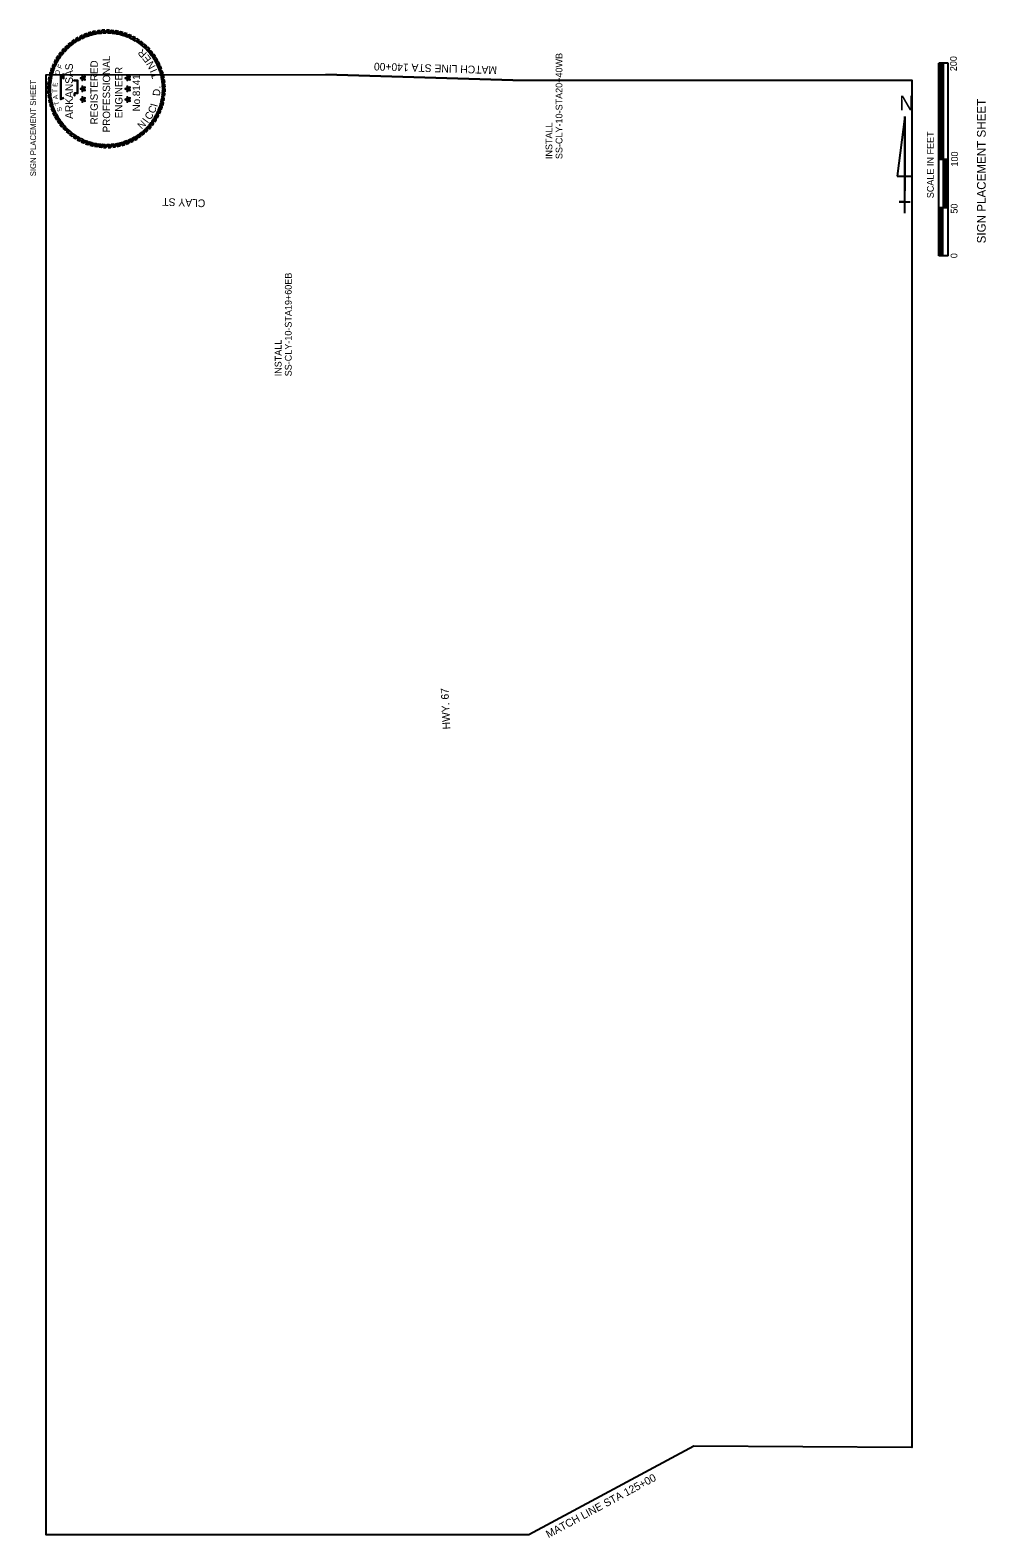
# Model space of a CAD drawing. Extents: x 992072 to 994297, y 1841240 to 1845659.
# Drawn here: x 992072 to 993062, y 1841240 to 1842803 of the extents above; entities that cross this region are included whole.
import ezdxf

# ---------------------------------------------------------------- set-up
doc = ezdxf.new("R2010")
doc.units = 0
for name, color, linetype in [('5', 7, 'Continuous'), ('63', 7, 'Continuous'), ('G-ANNO-SYMB', 7, 'Continuous'), ('G-ANNO-TEXT', 7, 'Continuous'), ('Level 10', 7, 'Continuous'), ('Plan Notes', 7, 'Continuous'), ('R_Annotation', 7, 'Continuous'), ('R_No Plot', 7, 'Continuous')]:
    doc.layers.add(name, color=color, linetype=linetype)

msp = doc.modelspace()

# ---------------------------------------------------------------- linework, layer by layer
at = {"layer": '5'}
for p, q in [((992572.2, 1842751.1), (992378.4, 1842757)), ((992759.9, 1841335.3), (992589, 1841243.7))]:
    msp.add_line(p, q, dxfattribs=at)
at = {"layer": '63'}
for p, q in [((992978.4, 1842713.3), (992970.7, 1842651.7)), ((992978.4, 1842613.3), (992978.4, 1842713.3)), ((992978.4, 1842713.3), (992978.4, 1842636.4)), ((992970.7, 1842651.7), (992986.1, 1842651.7)), ((992978.4, 1842613.3), (992978.4, 1842636.4)), ((992978.4, 1842624.8), (992972.6, 1842624.8)), ((992972.6, 1842624.8), (992984.1, 1842624.8)), ((992978.4, 1842613.3), (992978.4, 1842624.8))]:
    msp.add_line(p, q, dxfattribs=at)
at = {"layer": 'G-ANNO-SYMB'}
for points in [[(992117.9, 1842793), (992115.8, 1842791.5), (992114.5, 1842787), (992116.7, 1842788.7)], [(992122, 1842795.4), (992119.8, 1842794.1), (992118.1, 1842789.7), (992120.5, 1842791.3)], [(992126.3, 1842797.5), (992123.9, 1842796.4), (992122, 1842792.2), (992124.4, 1842793.5)], [(992130.7, 1842799.3), (992128.3, 1842798.4), (992126, 1842794.3), (992128.6, 1842795.5)], [(992135.3, 1842800.7), (992132.8, 1842800), (992130.2, 1842796.1), (992132.8, 1842797.1)], [(992139.9, 1842801.8), (992137.4, 1842801.3), (992134.5, 1842797.6), (992137.2, 1842798.4)], [(992144.7, 1842802.5), (992142.1, 1842802.2), (992138.9, 1842798.8), (992141.7, 1842799.3)], [(992149.4, 1842802.8), (992146.8, 1842802.7), (992143.4, 1842799.5), (992146.2, 1842799.8)], [(992154.2, 1842802.8), (992151.6, 1842802.8), (992147.9, 1842800), (992150.7, 1842800.1)], [(992158.9, 1842802.3), (992156.3, 1842802.6), (992152.5, 1842800), (992155.3, 1842799.9)], [(992163.7, 1842801.5), (992161.1, 1842802), (992157, 1842799.8), (992159.8, 1842799.4)], [(992168.3, 1842800.4), (992165.8, 1842801.1), (992161.5, 1842799.1), (992164.3, 1842798.6)], [(992172.8, 1842798.9), (992170.3, 1842799.7), (992166, 1842798.1), (992168.7, 1842797.4)], [(992177.2, 1842797), (992174.8, 1842798.1), (992170.3, 1842796.8), (992173, 1842795.8)], [(992181.4, 1842794.8), (992179.1, 1842796), (992174.6, 1842795.1), (992177.1, 1842793.9)], [(992185.5, 1842792.2), (992183.3, 1842793.7), (992178.6, 1842793.1), (992181.1, 1842791.7)], [(992103.8, 1842780.2), (992102.2, 1842778.1), (992102.4, 1842773.5), (992104, 1842775.8)], [(992107, 1842783.8), (992105.2, 1842781.9), (992105, 1842777.2), (992106.8, 1842779.4)], [(992110.4, 1842787.1), (992108.5, 1842785.3), (992107.9, 1842780.7), (992109.8, 1842782.8)], [(992114, 1842790.2), (992112, 1842788.6), (992111.1, 1842784), (992113.2, 1842785.9)], [(992189.3, 1842789.4), (992187.2, 1842791), (992182.6, 1842790.8), (992184.9, 1842789.2)], [(992192.9, 1842786.2), (992191, 1842788), (992186.3, 1842788.2), (992188.5, 1842786.4)], [(992196.2, 1842782.8), (992194.4, 1842784.7), (992189.8, 1842785.3), (992191.9, 1842783.4)], [(992199.3, 1842779.2), (992197.7, 1842781.2), (992193.1, 1842782.1), (992195, 1842780.1)], [(992202.1, 1842775.3), (992200.6, 1842777.4), (992196.1, 1842778.7), (992197.8, 1842776.5)], [(992094.3, 1842763.7), (992093.5, 1842761.2), (992095.1, 1842756.9), (992095.9, 1842759.6)], [(992096.2, 1842768.1), (992095.2, 1842765.7), (992096.4, 1842761.2), (992097.4, 1842763.9)], [(992098.4, 1842772.3), (992097.2, 1842770), (992098.1, 1842765.5), (992099.3, 1842768)], [(992101, 1842776.4), (992099.5, 1842774.2), (992100.1, 1842769.5), (992101.5, 1842772)], [(992204.5, 1842771.2), (992203.2, 1842773.5), (992198.8, 1842775.1), (992200.4, 1842772.7)], [(992206.6, 1842766.9), (992205.5, 1842769.3), (992201.3, 1842771.2), (992202.7, 1842768.8)], [(992208.4, 1842762.5), (992207.5, 1842764.9), (992203.4, 1842767.2), (992204.6, 1842764.6)], [(992209.8, 1842757.9), (992209.1, 1842760.4), (992205.2, 1842763), (992206.2, 1842760.4)], [(992090.9, 1842749.8), (992090.6, 1842747.2), (992093.2, 1842743.4), (992093.3, 1842746.2)], [(992091.7, 1842754.5), (992091.2, 1842752), (992093.4, 1842747.9), (992093.8, 1842750.7)], [(992092.8, 1842759.2), (992092.1, 1842756.7), (992094.1, 1842752.4), (992094.6, 1842755.2)], [(992126.9, 1842753.2), (992126.1, 1842753.8), (992124.2, 1842753.2), (992126.1, 1842752.5)], [(992126.9, 1842753.2), (992127.3, 1842754.2), (992126.1, 1842755.8), (992126.1, 1842753.8)], [(992126.9, 1842753.2), (992126.1, 1842752.5), (992126.1, 1842750.5), (992127.3, 1842752.2)], [(992126.9, 1842753.2), (992128, 1842753.2), (992129.2, 1842754.8), (992127.3, 1842754.2)], [(992126.9, 1842753.2), (992127.3, 1842752.2), (992129.2, 1842751.5), (992128, 1842753.2)], [(992173.5, 1842753.2), (992172.6, 1842753.8), (992170.7, 1842753.2), (992172.6, 1842752.5)], [(992173.5, 1842753.2), (992173.8, 1842754.2), (992172.6, 1842755.8), (992172.6, 1842753.8)], [(992173.5, 1842753.2), (992172.6, 1842752.5), (992172.6, 1842750.5), (992173.8, 1842752.2)], [(992173.5, 1842753.2), (992174.6, 1842753.2), (992175.7, 1842754.8), (992173.8, 1842754.2)], [(992173.5, 1842753.2), (992173.8, 1842752.2), (992175.7, 1842751.5), (992174.6, 1842753.2)], [(992210.9, 1842753.3), (992210.4, 1842755.8), (992206.7, 1842758.7), (992207.5, 1842756)], [(992211.6, 1842748.6), (992211.3, 1842751.1), (992207.9, 1842754.3), (992208.4, 1842751.5)], [(992211.9, 1842743.8), (992211.8, 1842746.4), (992208.6, 1842749.8), (992209, 1842747)], [(992090.4, 1842745.1), (992090.4, 1842742.5), (992093.2, 1842738.8), (992093.1, 1842741.6)], [(992090.4, 1842740.3), (992090.5, 1842737.7), (992093.7, 1842734.3), (992093.4, 1842737.1)], [(992090.7, 1842735.6), (992091, 1842733), (992094.5, 1842729.8), (992093.9, 1842732.6)], [(992091.4, 1842730.8), (992091.9, 1842728.3), (992095.6, 1842725.4), (992094.8, 1842728.1)], [(992126.9, 1842742.1), (992126.1, 1842742.7), (992124.2, 1842742.1), (992126.1, 1842741.4)], [(992126.9, 1842730.9), (992126.1, 1842731.6), (992124.2, 1842730.9), (992126.1, 1842730.3)], [(992126.9, 1842742.1), (992127.3, 1842743.1), (992126.1, 1842744.7), (992126.1, 1842742.7)], [(992126.9, 1842742.1), (992126.1, 1842741.4), (992126.1, 1842739.4), (992127.3, 1842741)], [(992126.9, 1842730.9), (992127.3, 1842731.9), (992126.1, 1842733.6), (992126.1, 1842731.6)], [(992126.9, 1842730.9), (992126.1, 1842730.3), (992126.1, 1842728.3), (992127.3, 1842729.9)], [(992126.9, 1842742.1), (992128, 1842742.1), (992129.2, 1842743.7), (992127.3, 1842743.1)], [(992126.9, 1842742.1), (992127.3, 1842741), (992129.2, 1842740.4), (992128, 1842742.1)], [(992126.9, 1842730.9), (992128, 1842730.9), (992129.2, 1842732.6), (992127.3, 1842731.9)], [(992126.9, 1842730.9), (992127.3, 1842729.9), (992129.2, 1842729.3), (992128, 1842730.9)], [(992173.5, 1842742.1), (992172.6, 1842742.7), (992170.7, 1842742.1), (992172.6, 1842741.4)], [(992173.5, 1842730.9), (992172.6, 1842731.6), (992170.7, 1842730.9), (992172.6, 1842730.3)], [(992173.5, 1842742.1), (992173.8, 1842743.1), (992172.6, 1842744.7), (992172.6, 1842742.7)], [(992173.5, 1842742.1), (992172.6, 1842741.4), (992172.6, 1842739.4), (992173.8, 1842741)], [(992173.5, 1842730.9), (992173.8, 1842731.9), (992172.6, 1842733.6), (992172.6, 1842731.6)], [(992173.5, 1842730.9), (992172.6, 1842730.3), (992172.6, 1842728.3), (992173.8, 1842729.9)], [(992173.5, 1842742.1), (992174.6, 1842742.1), (992175.7, 1842743.7), (992173.8, 1842743.1)], [(992173.5, 1842742.1), (992173.8, 1842741), (992175.7, 1842740.4), (992174.6, 1842742.1)], [(992173.5, 1842730.9), (992174.6, 1842730.9), (992175.7, 1842732.6), (992173.8, 1842731.9)], [(992173.5, 1842730.9), (992173.8, 1842729.9), (992175.7, 1842729.3), (992174.6, 1842730.9)], [(992209.5, 1842724.9), (992210.2, 1842727.4), (992208.2, 1842731.7), (992207.7, 1842728.9)], [(992210.6, 1842729.6), (992211.1, 1842732.1), (992208.9, 1842736.2), (992208.5, 1842733.4)], [(992211.4, 1842734.3), (992211.7, 1842736.9), (992209.2, 1842740.7), (992209, 1842737.9)], [(992211.9, 1842739), (992211.9, 1842741.6), (992209.1, 1842745.3), (992209.2, 1842742.5)], [(992092.5, 1842726.2), (992093.2, 1842723.7), (992097.1, 1842721.1), (992096.1, 1842723.7)], [(992093.9, 1842721.6), (992094.8, 1842719.2), (992098.9, 1842716.9), (992097.7, 1842719.5)], [(992095.7, 1842717.2), (992096.8, 1842714.8), (992101, 1842712.9), (992099.7, 1842715.3)], [(992201.3, 1842707.7), (992202.8, 1842709.9), (992202.2, 1842714.6), (992200.8, 1842712.1)], [(992203.9, 1842711.8), (992205.1, 1842714.1), (992204.2, 1842718.7), (992203, 1842716.1)], [(992206.1, 1842716), (992207.2, 1842718.4), (992205.9, 1842722.9), (992204.9, 1842720.2)], [(992208, 1842720.4), (992208.8, 1842722.9), (992207.2, 1842727.2), (992206.5, 1842724.5)], [(992097.8, 1842712.9), (992099.1, 1842710.6), (992103.5, 1842709), (992101.9, 1842711.4)], [(992100.3, 1842708.8), (992101.7, 1842706.7), (992106.2, 1842705.4), (992104.5, 1842707.6)], [(992103, 1842704.9), (992104.7, 1842702.9), (992109.2, 1842702), (992107.3, 1842704.1)], [(992106.1, 1842701.3), (992107.9, 1842699.4), (992112.5, 1842698.8), (992110.4, 1842700.7)], [(992188.3, 1842693.9), (992190.3, 1842695.6), (992191.2, 1842700.1), (992189.2, 1842698.2)], [(992191.9, 1842697), (992193.8, 1842698.8), (992194.4, 1842703.4), (992192.5, 1842701.3)], [(992195.4, 1842700.3), (992197.1, 1842702.2), (992197.3, 1842706.9), (992195.5, 1842704.7)], [(992198.5, 1842703.9), (992200.1, 1842706), (992199.9, 1842710.6), (992198.3, 1842708.3)], [(992109.4, 1842697.9), (992111.4, 1842696.1), (992116, 1842695.9), (992113.8, 1842697.7)], [(992113, 1842694.7), (992115.1, 1842693.1), (992119.7, 1842693.3), (992117.4, 1842694.9)], [(992116.8, 1842691.9), (992119, 1842690.4), (992123.7, 1842691), (992121.2, 1842692.4)], [(992120.9, 1842689.3), (992123.2, 1842688.1), (992127.8, 1842689), (992125.2, 1842690.2)], [(992125.1, 1842687.1), (992127.5, 1842686), (992132, 1842687.3), (992129.3, 1842688.3)], [(992129.5, 1842685.2), (992132, 1842684.4), (992136.3, 1842686), (992133.6, 1842686.7)], [(992134, 1842683.7), (992136.6, 1842683), (992140.8, 1842685), (992138, 1842685.5)], [(992138.7, 1842682.6), (992141.2, 1842682.1), (992145.3, 1842684.3), (992142.5, 1842684.7)], [(992143.4, 1842681.8), (992146, 1842681.5), (992149.9, 1842684.1), (992147, 1842684.2)], [(992148.1, 1842681.3), (992150.7, 1842681.3), (992154.4, 1842684.1), (992151.6, 1842684)], [(992152.9, 1842681.3), (992155.5, 1842681.4), (992158.9, 1842684.6), (992156.1, 1842684.3)], [(992157.7, 1842681.6), (992160.2, 1842681.9), (992163.4, 1842685.4), (992160.7, 1842684.8)], [(992162.4, 1842682.3), (992164.9, 1842682.8), (992167.8, 1842686.5), (992165.1, 1842685.7)], [(992167, 1842683.4), (992169.5, 1842684.1), (992172.1, 1842688), (992169.5, 1842687)], [(992171.6, 1842684.8), (992174, 1842685.7), (992176.3, 1842689.8), (992173.7, 1842688.6)], [(992176, 1842686.6), (992178.4, 1842687.7), (992180.3, 1842691.9), (992177.9, 1842690.6)], [(992180.3, 1842688.7), (992182.6, 1842690), (992184.2, 1842694.4), (992181.8, 1842692.8)], [(992184.4, 1842691.1), (992186.5, 1842692.6), (992187.8, 1842697.1), (992185.6, 1842695.4)]]:
    msp.add_lwpolyline(points, close=True, dxfattribs=at)
for points in [[(992107, 1842732.3), (992104, 1842730.9), (992104, 1842755.4), (992106.5, 1842753.4), (992106.5, 1842755), (992106.5, 1842756.4), (992106.6, 1842757.8)], [(992106.9, 1842732.7), (992104.4, 1842731.5), (992104.3, 1842754.6), (992106.9, 1842752.6), (992106.9, 1842755), (992106.9, 1842756.4), (992107, 1842757.8)], [(992117, 1842751.3), (992117.4, 1842750.8), (992118.1, 1842750.6), (992119.4, 1842750.5), (992120.7, 1842750.5), (992120.7, 1842737.6), (992118.8, 1842737.6), (992118, 1842737.6), (992117.8, 1842736.7), (992117.8, 1842734.9), (992117.4, 1842734.6)], [(992117.3, 1842751.6), (992117.7, 1842751.1), (992118.2, 1842751), (992119.4, 1842750.9), (992121.1, 1842750.9), (992121.1, 1842737.2), (992118.8, 1842737.2), (992118.3, 1842737.2), (992118.2, 1842736.6), (992118.2, 1842734.7), (992117.6, 1842734.3)]]:
    msp.add_lwpolyline(points, dxfattribs=at)
at = {"layer": 'Level 10'}
for p, q in [((993013.7, 1842648.8), (993013.7, 1842768.8)), ((993023.3, 1842768.8), (993013.7, 1842768.8)), ((993014.5, 1842668.8), (993014.5, 1842768.8)), ((993015.3, 1842668.8), (993015.3, 1842768.8)), ((993016.1, 1842668.8), (993016.1, 1842768.8)), ((993016.9, 1842668.8), (993016.9, 1842768.8)), ((993017.7, 1842668.8), (993017.7, 1842768.8)), ((993018.5, 1842668.8), (993018.5, 1842768.8)), ((993023.3, 1842568.8), (993023.3, 1842768.8)), ((993013.7, 1842568.8), (993013.7, 1842728.8)), ((993018.5, 1842668.8), (993018.5, 1842728.8)), ((993023.3, 1842668.8), (993013.7, 1842668.8)), ((993018.5, 1842618.8), (993018.5, 1842668.8)), ((993019.3, 1842618.8), (993019.3, 1842668.8)), ((993020.1, 1842618.8), (993020.1, 1842668.8)), ((993020.9, 1842618.8), (993020.9, 1842668.8)), ((993021.7, 1842618.8), (993021.7, 1842668.8)), ((993022.5, 1842618.8), (993022.5, 1842668.8)), ((993023.3, 1842608.8), (993023.3, 1842648.8)), ((993023.3, 1842618.8), (993013.7, 1842618.8)), ((993013.7, 1842568.8), (993013.7, 1842608.8)), ((993014.5, 1842568.8), (993014.5, 1842618.8)), ((993015.3, 1842568.8), (993015.3, 1842618.8)), ((993016.1, 1842568.8), (993016.1, 1842618.8)), ((993016.9, 1842568.8), (993016.9, 1842618.8)), ((993017.7, 1842568.8), (993017.7, 1842618.8)), ((993023.3, 1842568.8), (993013.7, 1842568.8))]:
    msp.add_line(p, q, dxfattribs=at)
at = {"layer": 'R_No Plot'}
msp.add_lwpolyline([(992589, 1841243.7), (992088.8, 1841243.7), (992088.8, 1842756.5), (992378.4, 1842757), (992572.2, 1842751.1), (992985.8, 1842751.1), (992985.8, 1841333.9), (992759.9, 1841335.3)], close=True, dxfattribs=at)

# ---------------------------------------------------------------- texts
at = {"layer": '63'}
msp.add_text('N', height=15.4, rotation=360, dxfattribs=at).set_placement((992972.7, 1842719.7))
at = {"layer": 'G-ANNO-SYMB'}
for s, height, rotation, p in [('R', 7.64, 135.478, (992193.5, 1842778.9)), ('E', 7.64, 127.6498, (992198.1, 1842772.8)), ('O', 4.84, 71.2218, (992102, 1842755.7)), ('F', 4.84, 65.3628, (992104.5, 1842762.3)), ('ARKANSAS', 7.89, 90, (992116.4, 1842710.9)), ('REGISTERED', 7.64, 90, (992142.2, 1842705.1)), ('PROFESSIONAL', 7.642, 90, (992155, 1842696.9)), ('ENGINEER', 7.64, 90, (992167.8, 1842711.5)), ('N', 7.64, 118.7033, (992202.3, 1842765.1)), ('I', 7.64, 114.2301, (992204, 1842761)), ('E', 4.84, 86.672, (992100.3, 1842744)), ('No.8141', 7.61, 90, (992186, 1842718.6)), ('T', 7.64, 106.7747, (992206, 1842754)), ('T', 4.84, 91.4789, (992100.2, 1842737.8)), ('A', 4.84, 98.6788, (992101.1, 1842731.6)), ('D', 7.64, 86.6451, (992206.7, 1842734.4)), ('.', 7.64, 94.846, (992207.3, 1842742.4)), ('T', 4.84, 106.9015, (992102.7, 1842725.7)), ('S', 4.84, 109.7726, (992105.4, 1842719.5)), ('C', 7.64, 58.6873, (992196.7, 1842709.2)), ('C', 7.64, 66.5155, (992200.7, 1842715.8)), ('I', 7.64, 74.3437, (992203.8, 1842722.8)), ('N', 7.64, 45.2676, (992187.8, 1842699.6)), ('I', 7.64, 54.2141, (992194, 1842705.8))]:
    msp.add_text(s, height=height, rotation=rotation, dxfattribs=at).set_placement(p)
at = {"layer": 'G-ANNO-TEXT'}
for height, p in [(6, (992078.2, 1842651.4)), (9, (993062.3, 1842581.9))]:
    msp.add_text('SIGN PLACEMENT SHEET', height=height, rotation=90, dxfattribs=at).set_placement(p)
at = {"layer": 'Level 10'}
for s, height, p in [('200', 7, (993032.4, 1842760.3)), ('SCALE IN FEET', 7.001, (993008.5, 1842628.7)), ('100', 7, (993033.5, 1842661.5)), ('50', 7, (993033.1, 1842612.7)), ('0', 7, (993032.9, 1842566.5))]:
    msp.add_text(s, height=height, rotation=90.0003, dxfattribs=at).set_placement(p)
at = {"layer": 'Plan Notes'}
for s, rotation, p in [('MATCH LINE STA 140+00', 178.266, (992556, 1842765.3)), ('CLAY ST', 177.9024, (992253.8, 1842627.3)), ('HWY. 67', 92.5306, (992507.5, 1842078.4)), ('MATCH LINE STA 125+00', 28.1934, (992609.2, 1841240))]:
    msp.add_text(s, height=8, rotation=rotation, dxfattribs=at).set_placement(p)
at = {"layer": 'R_Annotation'}
for s, p in [('SS-CLY-10-STA20+40WB', (992623.7, 1842669.2)), ('INSTALL', (992613.2, 1842669.2)), ('SS-CLY-10-STA19+60EB', (992343.1, 1842444.1)), ('INSTALL', (992332.6, 1842444.1))]:
    msp.add_text(s, height=7, rotation=90, dxfattribs=at).set_placement(p)

doc.saveas('drawing.dxf')
